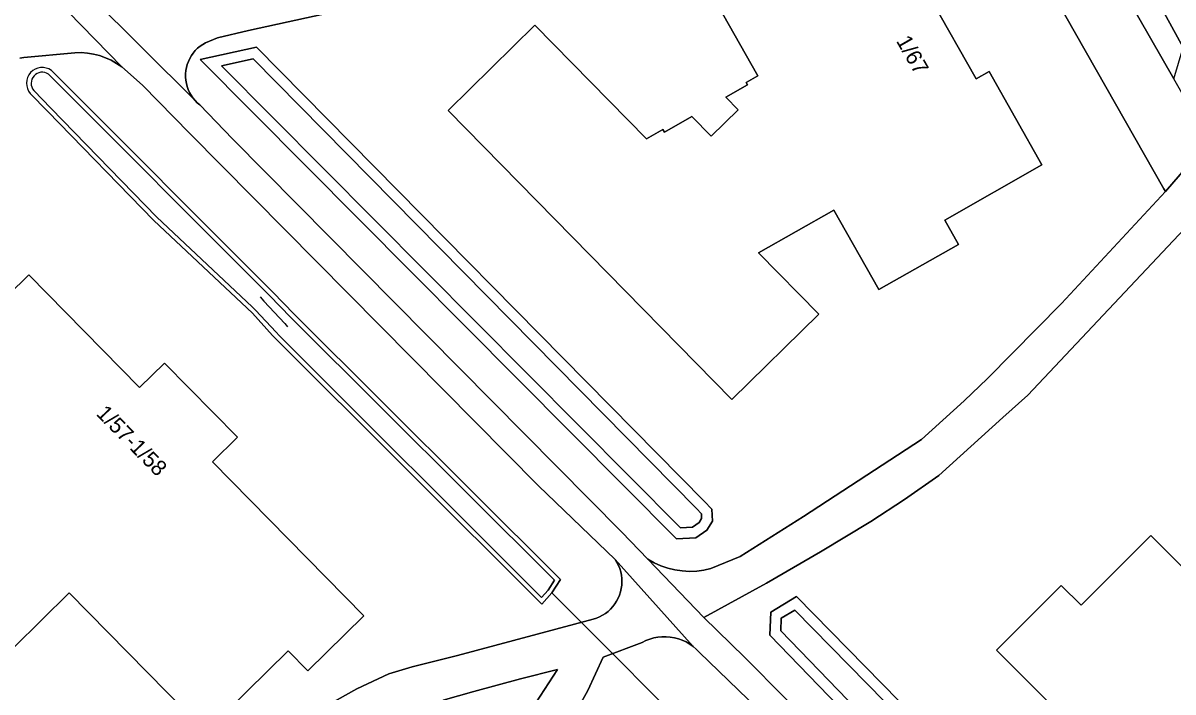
# Model space of a CAD drawing. Extents: x 162788 to 163838, y 385791 to 386523.
# Drawn here: x 162998.4 to 163072, y 386105.3 to 386148.1 of the extents above; entities that cross this region are included whole.
import ezdxf

# ---------------------------------------------------------------- set-up
doc = ezdxf.new("R2010")
doc.units = 0
for name, color, linetype in [('IMGEO_Duiker', 7, 'Continuous'), ('IMGEO_Erf', 7, 'Continuous'), ('IMGEO_Groenvoorziening', 7, 'Continuous'), ('IMGEO_Oever', 7, 'Continuous'), ('IMGEO_Pand', 7, 'Continuous'), ('IMGEO_Pand_nummerreeks', 7, 'Continuous'), ('IMGEO_Parkeervlak_open', 7, 'Continuous'), ('IMGEO_Waterloop', 7, 'Continuous'), ('IMGEO_Woonerf_gesloten', 7, 'Continuous'), ('IMGEO_Woonerf_open', 7, 'Continuous')]:
    doc.layers.add(name, color=color, linetype=linetype)

msp = doc.modelspace()

# ---------------------------------------------------------------- linework, layer by layer
at = {"layer": 'IMGEO_Duiker'}
for points in [[(163013.606, 386130.548), (163013.858, 386130.277), (163015.184, 386128.849), (163015.373, 386128.646)], [(163040.322, 386103.541), (163039.625, 386104.242), (163038.928, 386104.942), (163036.097, 386107.787), (163032.291, 386111.607)]]:
    msp.add_lwpolyline(points, dxfattribs=at)
at = {"layer": 'IMGEO_Erf'}
for points in [[(163019.609, 386149.062), (163012.878, 386147.609), (163010.885, 386147.124), (163010.111, 386146.819), (163009.934, 386146.715), (163009.765, 386146.596), (163009.608, 386146.463), (163009.463, 386146.317), (163009.331, 386146.159), (163009.213, 386145.991), (163009.11, 386145.812), (163009.023, 386145.626), (163008.952, 386145.433), (163008.898, 386145.234), (163008.862, 386145.031), (163008.843, 386144.827), (163008.842, 386144.621), (163008.858, 386144.416), (163008.893, 386144.213), (163008.944, 386144.013), (163009.013, 386143.819), (163009.098, 386143.632), (163009.199, 386143.453), (163009.315, 386143.283), (163009.445, 386143.123), (163009.589, 386142.976), (163009.745, 386142.841), (163011.853, 386140.665), (163036.77, 386115.488), (163038.435, 386113.764), (163038.84, 386113.535), (163039.266, 386113.344), (163039.706, 386113.193), (163040.159, 386113.083), (163040.62, 386113.015), (163041.086, 386112.99), (163041.551, 386113.008), (163042.013, 386113.068), (163042.468, 386113.17), (163044.33, 386113.933), (163048.378, 386116.505), (163055.946, 386121.437), (163058.676, 386123.893), (163060.174, 386125.341), (163064.896, 386130.133), (163071.555, 386137.294), (163071.455, 386137.47), (163050.858, 386173.695)], [(163056.61, 386149.496), (163059.436, 386144.503), (163060.268, 386144.973), (163063.651, 386138.994), (163057.429, 386135.473), (163058.31, 386133.915), (163053.202, 386131.024), (163050.33, 386136.098), (163045.512, 386133.371), (163049.367, 386129.449), (163043.811, 386123.989), (163025.644, 386142.471), (163031.2, 386147.932), (163038.338, 386140.67), (163039.391, 386141.266), (163039.482, 386141.104), (163041.25, 386142.105), (163042.485, 386140.848), (163044.197, 386142.53), (163043.412, 386143.328), (163044.804, 386144.116), (163044.712, 386144.278), (163045.461, 386144.702), (163040.571, 386153.344)], [(163018.012, 386104.467), (163019.81, 386105.476), (163021.839, 386106.427), (163023.35, 386106.882), (163026.238, 386107.611), (163034.928, 386109.929), (163035.134, 386109.995), (163035.333, 386110.078), (163035.524, 386110.179), (163035.706, 386110.295), (163035.877, 386110.427), (163036.036, 386110.573), (163036.182, 386110.732), (163036.313, 386110.903), (163036.429, 386111.085), (163036.529, 386111.276), (163036.613, 386111.475), (163036.678, 386111.681), (163036.726, 386111.891), (163036.755, 386112.105), (163036.766, 386112.321), (163036.758, 386112.536), (163036.732, 386112.751), (163036.687, 386112.962), (163036.624, 386113.168), (163036.544, 386113.369), (163036.446, 386113.561), (163036.332, 386113.744), (163031.422, 386118.469), (163009.12, 386141.019), (163006.091, 386144.101), (163004.756, 386145.273), (163004.426, 386145.499), (163004.078, 386145.694), (163003.713, 386145.859), (163003.336, 386145.991), (163002.948, 386146.09), (163002.554, 386146.154), (163002.155, 386146.184), (163001.755, 386146.179), (162998.479, 386145.875), (162998.224, 386145.839)], [(163000.253, 386145.044), (163014.422, 386130.866), (163015.785, 386129.44), (163032.844, 386112.459), (163032.291, 386111.607), (163031.64, 386110.887), (163014.409, 386128.087)], [(163014.409, 386128.087), (163013.116, 386129.503), (163006.801, 386135.446), (163000, 386142.43), (162998.904, 386143.569)], [(163073.094, 386135.242), (163062.743, 386124.268), (163061.153, 386122.841), (163057.044, 386119.123), (163054.851, 386117.586), (163052.69, 386116.175), (163049.482, 386114.233), (163046.013, 386112.237), (163042.009, 386110.032), (163044.609, 386107.498), (163057.742, 386094.28)], [(162993.526, 386126.784), (162998.804, 386131.971), (163005.895, 386124.757), (163007.488, 386126.323), (163012.159, 386121.57), (163010.566, 386120.004), (163020.251, 386110.151), (163016.671, 386106.632), (163015.416, 386107.909), (163010.138, 386102.721), (163001.39, 386111.622), (162996.056, 386106.378)], [(163068.212, 386100.47), (163060.737, 386107.943), (163064.887, 386112.094), (163066.153, 386110.828), (163070.608, 386115.284), (163075.013, 386110.879), (163075.636, 386111.501), (163080.569, 386106.569), (163079.947, 386105.947), (163086.012, 386099.882)], [(163054.386, 386100.491), (163046.244, 386108.909), (163046.302, 386110.387), (163047.932, 386111.375), (163063.284, 386095.753)], [(163049.21, 386100.56), (163041.713, 386107.825), (163041.525, 386108.014), (163041.321, 386108.185), (163041.103, 386108.338), (163040.872, 386108.471), (163040.63, 386108.583), (163040.38, 386108.673), (163040.122, 386108.741), (163039.859, 386108.785), (163039.593, 386108.806), (163039.327, 386108.804), (163039.062, 386108.778), (163038.8, 386108.728), (163038.544, 386108.655), (163038.295, 386108.56), (163038.055, 386108.444), (163035.569, 386107.508), (163034.593, 386105.372), (163032.927, 386102.387)]]:
    msp.add_lwpolyline(points, dxfattribs=at)
msp.add_lwpolyline([(163042.032, 386117.481), (163042.526, 386116.965), (163042.56, 386116.199), (163042.207, 386115.628), (163041.506, 386115.145), (163040.251, 386115.066), (163009.77, 386145.742), (163013.387, 386146.525)], close=True, dxfattribs=at)
msp.add_arc((162999.668, 386144.225), 1.007, 54.44998, 220.65943, dxfattribs=at)
at = {"layer": 'IMGEO_Groenvoorziening'}
for points in [[(163065.544, 386159.577), (163072.693, 386146.51)], [(163029.314, 386101.599), (163032.635, 386106.713), (163030.28, 386106.104), (163027.296, 386105.296), (163025.32, 386104.75)]]:
    msp.add_lwpolyline(points, dxfattribs=at)
at = {"layer": 'IMGEO_Oever'}
for points in [[(163013.387, 386146.525), (163009.77, 386145.742), (163040.251, 386115.066), (163041.506, 386115.145), (163042.207, 386115.628), (163042.56, 386116.199), (163042.526, 386116.965), (163042.032, 386117.481)], [(163041.543, 386117.006), (163041.856, 386116.679), (163041.869, 386116.379), (163041.702, 386116.108), (163041.275, 386115.814), (163040.517, 386115.766), (163011.132, 386145.339), (163013.165, 386145.779)], [(163061.138, 386093.665), (163061.627, 386094.141), (163054.874, 386100.968), (163046.937, 386109.174), (163046.969, 386109.994), (163047.824, 386110.512), (163062.795, 386095.277), (163063.284, 386095.753), (163047.932, 386111.375), (163046.302, 386110.387), (163046.244, 386108.909), (163054.386, 386100.491)]]:
    msp.add_lwpolyline(points, close=True, dxfattribs=at)
for points in [[(162998.904, 386143.569), (163000, 386142.43), (163006.801, 386135.446), (163013.116, 386129.503), (163014.409, 386128.087), (163031.64, 386110.887), (163032.291, 386111.607), (163032.844, 386112.459), (163015.785, 386129.44), (163014.422, 386130.866), (163000.253, 386145.044)], [(163000.061, 386144.814), (163014.005, 386130.862), (163014.212, 386130.647), (163015.577, 386129.235), (163015.784, 386129.021), (163032.462, 386112.418), (163032.054, 386111.789), (163031.629, 386111.319), (163014.833, 386128.085)], [(163014.833, 386128.085), (163014.628, 386128.303), (163013.31, 386129.705), (163013.105, 386129.923), (163007.01, 386135.659), (163000.214, 386142.637), (162999.125, 386143.769)]]:
    msp.add_lwpolyline(points, dxfattribs=at)
for radius, start, end in [(1.007, 54.44998, 220.65943), (0.709, 56.29311, 220.00568)]:
    msp.add_arc((162999.668, 386144.225), radius, start, end, dxfattribs=at)
at = {"layer": 'IMGEO_Pand'}
for points in [[(163040.571, 386153.344), (163045.461, 386144.702), (163044.712, 386144.278), (163044.804, 386144.116), (163043.412, 386143.328), (163044.197, 386142.53), (163042.485, 386140.848), (163041.25, 386142.105), (163039.482, 386141.104), (163039.391, 386141.266), (163038.338, 386140.67), (163031.2, 386147.932), (163025.644, 386142.471), (163043.811, 386123.989), (163049.367, 386129.449), (163045.512, 386133.371), (163050.33, 386136.098), (163053.202, 386131.024), (163058.31, 386133.915), (163057.429, 386135.473), (163063.651, 386138.994), (163060.268, 386144.973), (163059.436, 386144.503), (163056.61, 386149.496)], [(162996.056, 386106.378), (163001.39, 386111.622), (163010.138, 386102.721), (163015.416, 386107.909), (163016.671, 386106.632), (163020.251, 386110.151), (163010.566, 386120.004), (163012.159, 386121.57), (163007.488, 386126.323), (163005.895, 386124.757), (162998.804, 386131.971), (162993.526, 386126.784)], [(163086.012, 386099.882), (163079.947, 386105.947), (163080.569, 386106.569), (163075.636, 386111.501), (163075.013, 386110.879), (163070.608, 386115.284), (163066.153, 386110.828), (163064.887, 386112.094), (163060.737, 386107.943), (163068.212, 386100.47)]]:
    msp.add_lwpolyline(points, dxfattribs=at)
at = {"layer": 'IMGEO_Parkeervlak_open'}
msp.add_lwpolyline([(163063.122, 386160.144), (163072.09, 386144.501), (163072.693, 386146.51), (163065.544, 386159.577)], close=True, dxfattribs=at)
at = {"layer": 'IMGEO_Waterloop'}
for points in [[(163013.165, 386145.779), (163011.132, 386145.339), (163040.517, 386115.766), (163041.275, 386115.814), (163041.702, 386116.108), (163041.869, 386116.379), (163041.856, 386116.679), (163041.543, 386117.006)], [(163047.824, 386110.512), (163046.969, 386109.994), (163046.937, 386109.174), (163054.874, 386100.968), (163061.627, 386094.141), (163062.795, 386095.277)]]:
    msp.add_lwpolyline(points, close=True, dxfattribs=at)
msp.add_lwpolyline([(162999.125, 386143.769), (163000.214, 386142.637), (163007.01, 386135.659), (163013.105, 386129.923), (163013.31, 386129.705), (163014.628, 386128.303), (163014.833, 386128.085), (163031.629, 386111.319), (163032.054, 386111.789), (163032.462, 386112.418), (163015.784, 386129.021), (163015.577, 386129.235), (163014.212, 386130.647), (163014.005, 386130.862), (163000.061, 386144.814)], dxfattribs=at)
msp.add_arc((162999.668, 386144.225), 0.709, 56.29311, 220.00568, dxfattribs=at)
at = {"layer": 'IMGEO_Woonerf_gesloten'}
for points in [[(162998.224, 386145.839), (162998.479, 386145.875), (163001.755, 386146.179), (163002.155, 386146.184), (163002.554, 386146.154), (163002.948, 386146.09), (163003.336, 386145.991), (163003.713, 386145.859), (163004.078, 386145.694), (163004.426, 386145.499), (163004.756, 386145.273), (162997.883, 386152.342)], [(163002.732, 386149.828), (163009.445, 386143.123), (163009.315, 386143.283), (163009.199, 386143.453), (163009.098, 386143.632), (163009.013, 386143.819), (163008.944, 386144.013), (163008.893, 386144.213), (163008.858, 386144.416), (163008.842, 386144.621), (163008.843, 386144.827), (163008.862, 386145.031), (163008.898, 386145.234), (163008.952, 386145.433), (163009.023, 386145.626), (163009.11, 386145.812), (163009.213, 386145.991), (163009.331, 386146.159), (163009.463, 386146.317), (163009.608, 386146.463), (163009.765, 386146.596), (163009.934, 386146.715), (163010.111, 386146.819), (163010.885, 386147.124), (163012.878, 386147.609), (163019.609, 386149.062)], [(163074.529, 386140.723), (163071.555, 386137.294), (163064.896, 386130.133), (163060.174, 386125.341), (163058.676, 386123.893), (163055.946, 386121.437), (163048.378, 386116.505), (163044.33, 386113.933), (163042.468, 386113.17), (163042.013, 386113.068), (163041.551, 386113.008), (163041.086, 386112.99), (163040.62, 386113.015), (163040.159, 386113.083), (163039.706, 386113.193), (163039.266, 386113.344), (163038.84, 386113.535), (163038.435, 386113.764), (163042.009, 386110.032), (163046.013, 386112.237), (163049.482, 386114.233), (163052.69, 386116.175), (163054.851, 386117.586), (163057.044, 386119.123), (163061.153, 386122.841), (163062.743, 386124.268), (163073.094, 386135.242)], [(163032.927, 386102.387), (163034.593, 386105.372), (163035.569, 386107.508), (163038.055, 386108.444), (163038.295, 386108.56), (163038.544, 386108.655), (163038.8, 386108.728), (163039.062, 386108.778), (163039.327, 386108.804), (163039.593, 386108.806), (163039.859, 386108.785), (163040.122, 386108.741), (163040.38, 386108.673), (163040.63, 386108.583), (163040.872, 386108.471), (163041.103, 386108.338), (163041.321, 386108.185), (163036.332, 386113.744), (163036.446, 386113.561), (163036.544, 386113.369), (163036.624, 386113.168), (163036.687, 386112.962), (163036.732, 386112.751), (163036.758, 386112.536), (163036.766, 386112.321), (163036.755, 386112.105), (163036.726, 386111.891), (163036.678, 386111.681), (163036.613, 386111.475), (163036.529, 386111.276), (163036.429, 386111.085), (163036.313, 386110.903), (163036.182, 386110.732), (163036.036, 386110.573), (163035.877, 386110.427), (163035.706, 386110.295), (163035.524, 386110.179), (163035.333, 386110.078), (163035.134, 386109.995), (163034.928, 386109.929), (163026.238, 386107.611), (163023.35, 386106.882), (163021.839, 386106.427), (163019.81, 386105.476), (163018.012, 386104.467)], [(163025.32, 386104.75), (163027.296, 386105.296), (163030.28, 386106.104), (163032.635, 386106.713), (163029.314, 386101.599)]]:
    msp.add_lwpolyline(points, dxfattribs=at)
at = {"layer": 'IMGEO_Woonerf_open'}
for points in [[(162937.328, 386213.523), (162970.367, 386180.135), (162997.883, 386152.342), (163004.756, 386145.273), (163006.091, 386144.101), (163009.12, 386141.019), (163031.422, 386118.469), (163036.332, 386113.744), (163041.321, 386108.185), (163041.525, 386108.014), (163041.713, 386107.825), (163049.21, 386100.56)], [(163057.742, 386094.28), (163044.609, 386107.498), (163042.009, 386110.032), (163038.435, 386113.764), (163036.77, 386115.488), (163011.853, 386140.665), (163009.745, 386142.841), (163009.589, 386142.976), (163009.445, 386143.123), (163002.732, 386149.828), (162976.869, 386175.895)]]:
    msp.add_lwpolyline(points, dxfattribs=at)
msp.add_lwpolyline([(163063.122, 386160.144), (163054.328, 386175.482), (163050.858, 386173.695), (163071.455, 386137.47), (163071.555, 386137.294), (163074.529, 386140.723), (163074.174, 386140.866), (163072.09, 386144.501)], close=True, dxfattribs=at)

# ---------------------------------------------------------------- texts
at = {"layer": 'IMGEO_Pand_nummerreeks'}
for s, rotation, p in [('1/67', 299.70474, (163054.293, 386146.936)), ('1/57-1/58', 314.52754, (163003.068, 386123.031))]:
    msp.add_text(s, height=1, rotation=rotation, dxfattribs=at).set_placement(p)

doc.saveas('drawing.dxf')
